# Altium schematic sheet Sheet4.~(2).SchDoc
size A4; SheetNumber: 2; SheetTotal: 2
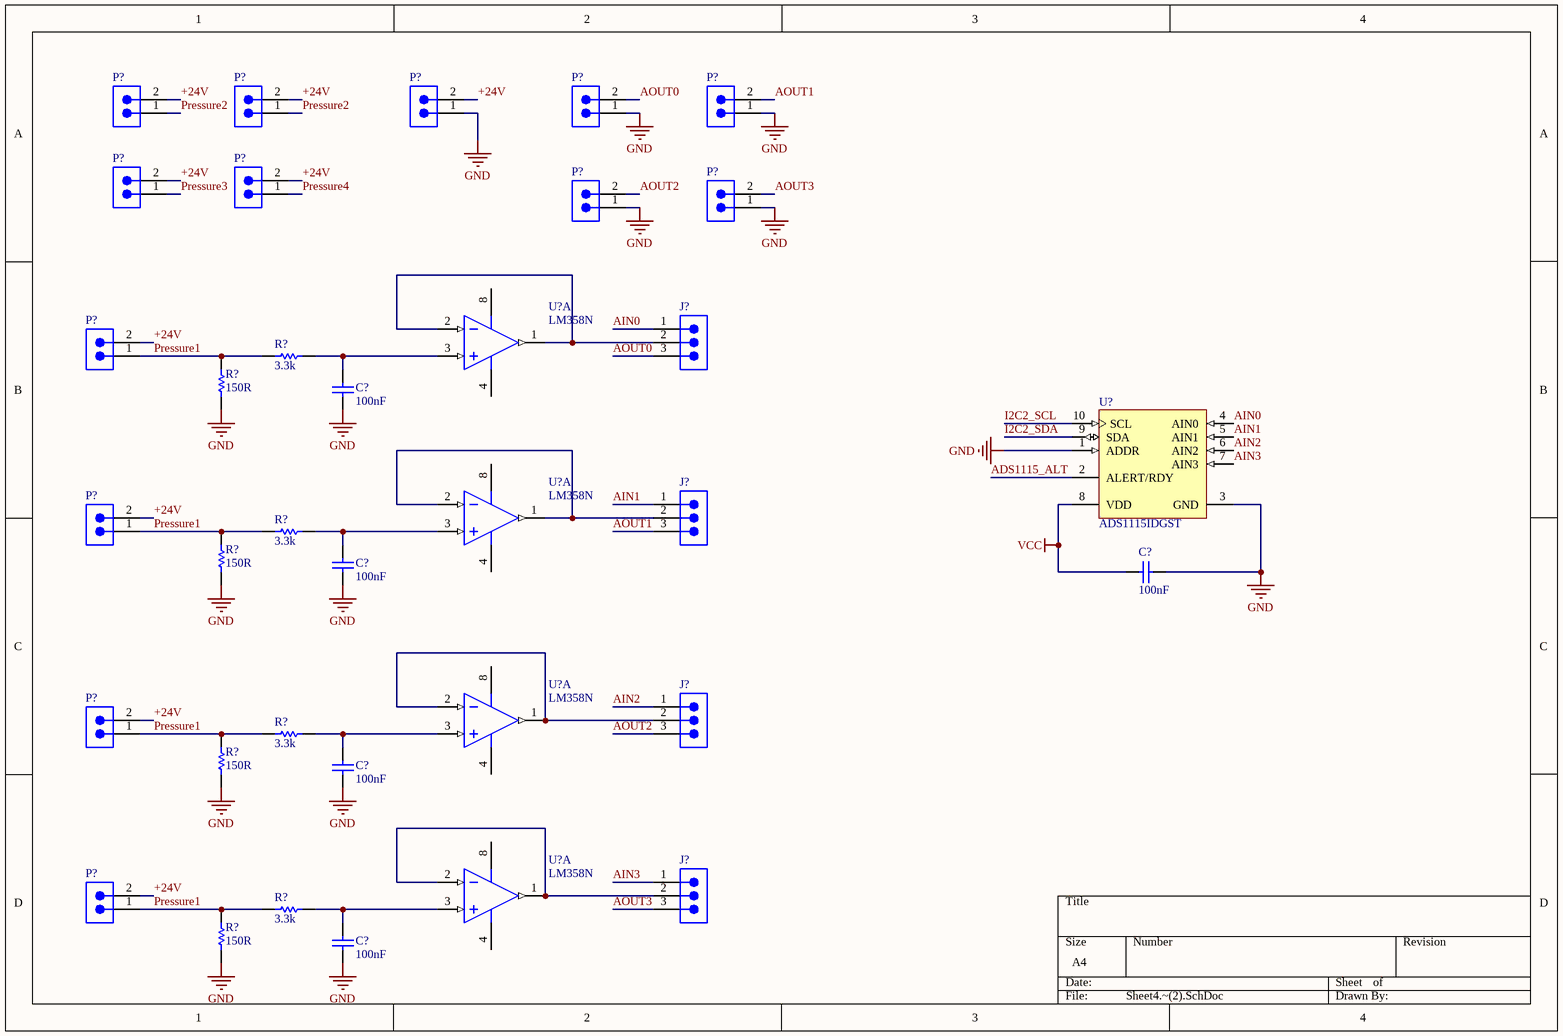
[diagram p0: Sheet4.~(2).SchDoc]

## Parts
(Parts that share a designator on the sheet are numbered #1, #2 ... from top to bottom, then left to right.)
C?#1  value 100nF  (hidden comment: Capacitor)
C?#2  value 100nF  (hidden comment: Capacitor)
C?#3  value 100nF  (hidden comment: Capacitor)
C?#4  value 100nF  (hidden comment: Capacitor)
C?#5  value 100nF  (hidden comment: Capacitor)
J?#1  (no value)  [679303124022]
J?#2  (no value)  [679303124022]
J?#3  (no value)  [679303124022]
J?#4  (no value)  [679303124022]
P?#1  (no value)  [620302124022]
P?#2  (no value)  [620302124022]
P?#3  (no value)  [620302124022]
P?#4  (no value)  [620302124022]
P?#5  (no value)  [620302124022]
P?#6  (no value)  [620302124022]
P?#7  (no value)  [620302124022]
P?#8  (no value)  [620302124022]
P?#9  (no value)  [620302124022]
P?#10  (no value)  [620302124022]
P?#11  (no value)  [620302124022]
P?#12  (no value)  [620302124022]
P?#13  (no value)  [620302124022]
R?#1  value 3.3k  (hidden comment: Resistor)
R?#2  value 150R  (hidden comment: Resistor)
R?#3  value 3.3k  (hidden comment: Resistor)
R?#4  value 150R  (hidden comment: Resistor)
R?#5  value 3.3k  (hidden comment: Resistor)
R?#6  value 150R  (hidden comment: Resistor)
R?#7  value 3.3k  (hidden comment: Resistor)
R?#8  value 150R  (hidden comment: Resistor)
U?#1  LM358N  [ONSC-PDIP-8-626-05_M]  (part A of 2)
U?#2  ADS1115IDGST  [TI-DGS10_M]
U?#3  LM358N  [ONSC-PDIP-8-626-05_M]  (part A of 2)
U?#4  LM358N  [ONSC-PDIP-8-626-05_M]  (part A of 2)
U?#5  LM358N  [ONSC-PDIP-8-626-05_M]  (part A of 2)

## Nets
GND: C?#1.1 C?#2.1 C?#3.1 C?#4.1 C?#5.1 P?#3.1 P?#4.1 P?#5.1 P?#8.1 P?#9.1 R?#2.1 R?#4.1 R?#6.1 R?#8.1 U?#2.1(ADDR) U?#2.3(GND)
VCC: C?#2.2 U?#2.8(VDD)
+24V: P?#1.2 P?#2.2 P?#3.2 P?#6.2 P?#7.2 P?#10.2 P?#11.2 P?#12.2 P?#13.2
ADS1115_ALT: U?#2.2(ALERT/RDY)
AIN0: J?#1.1 U?#2.4(AIN0)
AIN1: J?#2.1 U?#2.5(AIN1)
AIN2: J?#3.1 U?#2.6(AIN2)
AIN3: J?#4.1 U?#2.7(AIN3)
AOUT0: J?#1.3 P?#4.2
AOUT1: J?#2.3 P?#5.2
AOUT2: J?#3.3 P?#8.2
AOUT3: J?#4.3 P?#9.2
I2C2_SCL: U?#2.10(SCL)
I2C2_SDA: U?#2.9(SDA)
Pressure1: P?#10.1 P?#11.1 P?#12.1 P?#13.1 R?#1.2 R?#2.2 R?#3.2 R?#4.2 R?#5.2 R?#6.2 R?#7.2 R?#8.2
Pressure2: P?#1.1 P?#2.1
Pressure3: P?#6.1
Pressure4: P?#7.1
NetC?#1_2: C?#1.2 R?#1.1 U?#1.3(INA+)
NetC?#3_2: C?#3.2 R?#3.1 U?#3.3(INA+)
NetC?#4_2: C?#4.2 R?#5.1 U?#4.3(INA+)
NetC?#5_2: C?#5.2 R?#7.1 U?#5.3(INA+)
NetJ?#1_2: J?#1.2 U?#1.1(OUTA) U?#1.2(INA-)
NetJ?#2_2: J?#2.2 U?#3.1(OUTA) U?#3.2(INA-)
NetJ?#3_2: J?#3.2 U?#4.1(OUTA) U?#4.2(INA-)
NetJ?#4_2: J?#4.2 U?#5.1(OUTA) U?#5.2(INA-)

Not connected (* = marked no-connect by the designer): U?#1 4(VEE/GND) 8(VCC); U?#3 4(VEE/GND) 8(VCC); U?#4 4(VEE/GND) 8(VCC); U?#5 4(VEE/GND) 8(VCC)

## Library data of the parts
C?#1-C?#5 = Capacitor: SimulationGenericComponent: True
J?#1-J?#4 = CMP-1502-00722-2: NexarPartId: 18818282; Insulation: Insulated; Operating Supply Voltage: 50V; Number of Contacts: 3; Current Rating: 1A; Insulation Resistance: 100MΩ; Gender: Male; Contact Resistance: 20mΩ; Connector Type: Male Pin; Pitch: 1.5mm
P?#1-P?#13 = CMP-1502-00660-2: NexarPartId: 18818242; Insulation: Insulated; Connector Type: Male Pin; Pitch: 2mm; Insulation Resistance: 1GΩ; Gender: Male; Voltage Rating: 125V; Number of Positions: 2; Contact Resistance: 20mΩ; Operating Supply Voltage: 100V; Current Rating: 2A
R?#1-R?#8 = Resistor: TC1: 0; SimulationGenericComponent: True
U?#1 U?#3-U?#5 = CMP-1310-00098-1: Single Supply Dual Operational Amplifier, 3 to 32 V, 0 to 70 degC, 8-Pin PDIP, Tube; Manufacturer: On Semiconductor; VCC Max (V): 32; VCC Min (V): 3
U?#2 = CMP-0003-00378-2: 16-Bit ADC with Integrated Multiplexer, PGA, Comparator, Oscillator, and Reference, -40 to 125 degC, 10-pin SOP (DGS10), Green (RoHS & no Sb/Br); Manufacturer: Texas Instruments; Sample Rate (max)(SPS): 860; SubFamily: Precision ADC (<=10MSPS); Architecture: Delta-Sigma; Digital Supply(Min)(V): 2; Resolution(Bits): 16; Digital Supply(Max)(V): 5.5; INL(Max)(+/-LSB): 1; Interface: Serial I2C; # Input Channels: 4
